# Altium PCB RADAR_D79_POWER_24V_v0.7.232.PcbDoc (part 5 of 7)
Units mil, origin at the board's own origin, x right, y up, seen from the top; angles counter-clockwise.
Board outline 3110.24 x 3110.24 mil, 8 copper layers (Top Layer, GND1, SIG1, PWR1, PWR2, SIG2, GND2, Bottom Layer), stack 55.2 mil thick; 304 components, 269 nets, 1408 pads, 1367 vias.
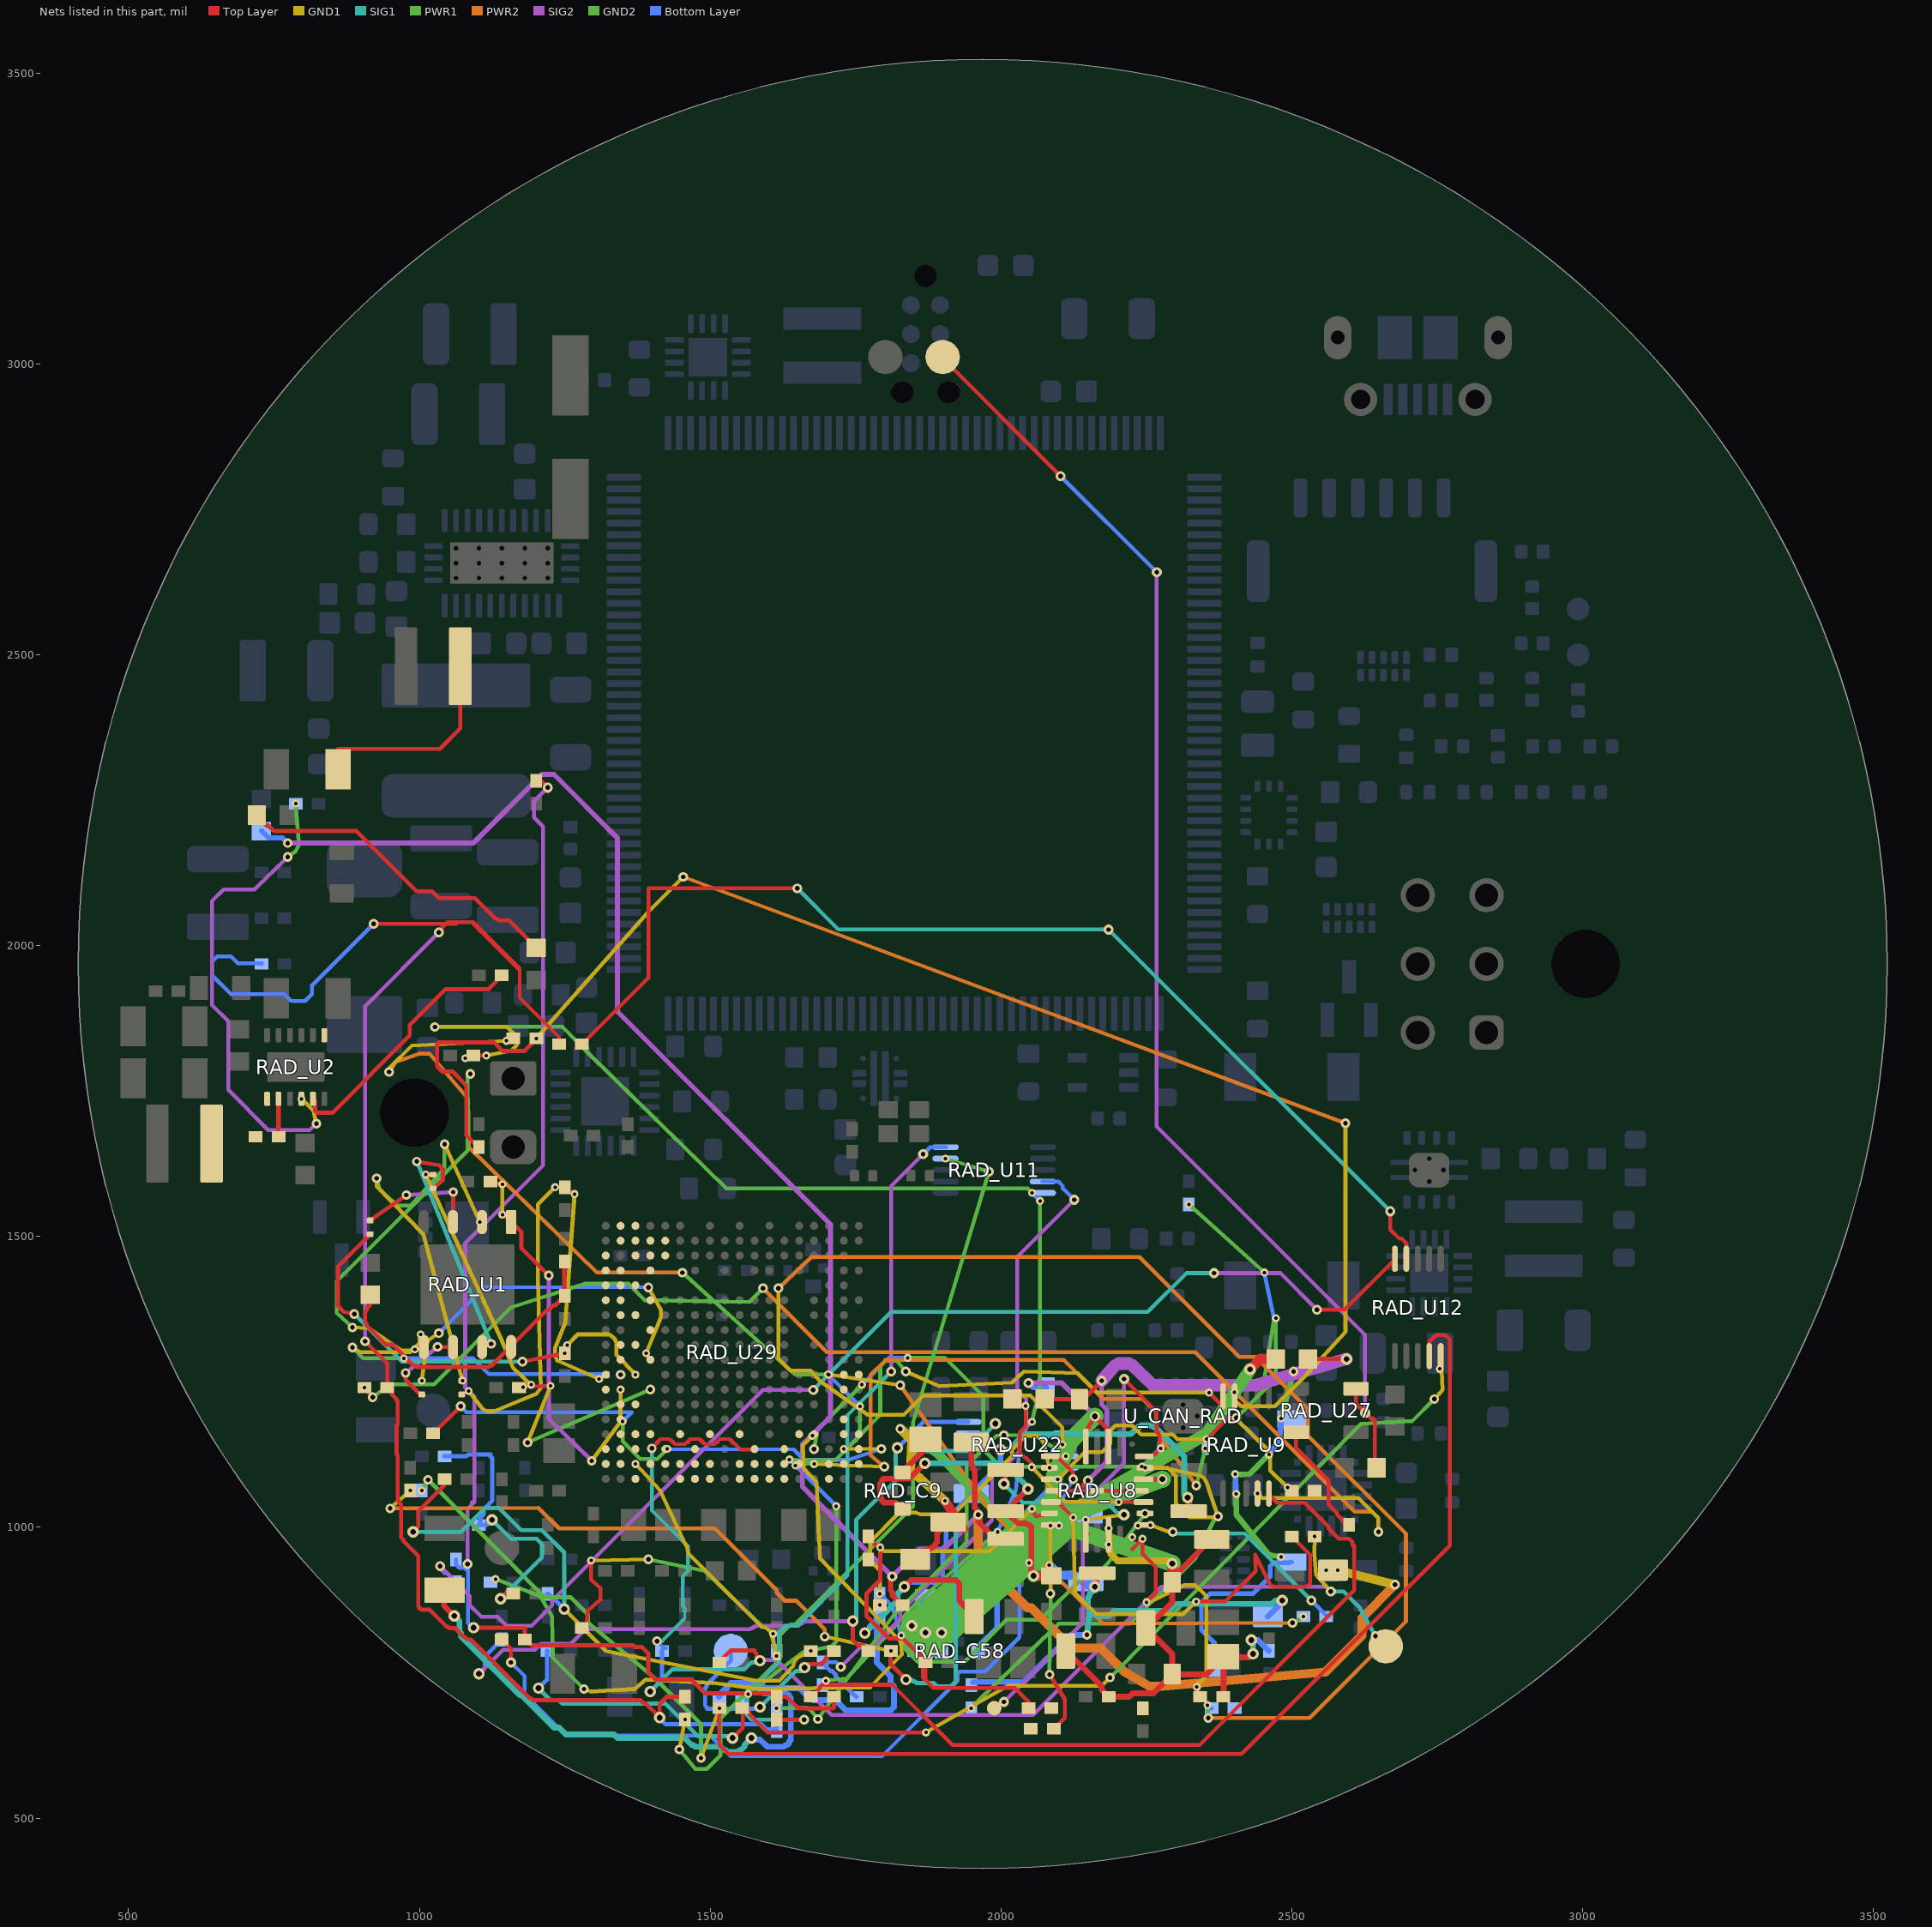
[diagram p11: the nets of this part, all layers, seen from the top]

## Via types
v1: diameter 13.77, hole 5.9, Top Layer to GND1, tented both sides, 393 vias
v2: diameter 16.54, hole 7.87, Top Layer to Bottom Layer, tented both sides, 129 vias
v3: diameter 19.68, hole 9.84, Top Layer to Bottom Layer, tented both sides, 126 vias
v4: diameter 13.77/13.77 (per signal layer), hole 5.9, Top Layer to GND1, tented both sides, 120 vias
v5: diameter 13.77, hole 5.9, Top Layer to GND1, tented top, 104 vias
v6: diameter 13.78, hole 5.91, Top Layer to GND1, tented both sides, 75 vias
v7: diameter 19.68, hole 9.84, Top Layer to Bottom Layer, 74 vias
v8: diameter 17.32, hole 7.87, Top Layer to Bottom Layer, tented both sides, 71 vias
v9: diameter 13.78, hole 5.91, GND2 to Bottom Layer, tented both sides, 64 vias
v10: diameter 13.78, hole 5.91, Top Layer to GND1, tented bottom, 39 vias
v11: diameter 13.78, hole 5.91, GND2 to Bottom Layer, tented top, 38 vias
v12: diameter 13.78, hole 5.91, Top Layer to GND1, 26 vias
v13: diameter 16.54, hole 7.87, GND2 to Bottom Layer, tented both sides, 22 vias
v14: diameter 16.54, hole 7.87, Top Layer to Bottom Layer, 19 vias
v15: diameter 22.05, hole 11.81, Top Layer to Bottom Layer, tented both sides, 17 vias
v16: diameter 13.78, hole 5.91, GND2 to Bottom Layer, 9 vias
v17: diameter 18.11, hole 9.06, Top Layer to Bottom Layer, 7 vias
v18: diameter 22.83, hole 11.81, Top Layer to Bottom Layer, 6 vias
v19: diameter 22.05, hole 11.81, Top Layer to Bottom Layer, 6 vias
v20: diameter 22.83, hole 11.81, Top Layer to Bottom Layer, tented both sides, 5 vias
v21: diameter 19.68, hole 7.87, Top Layer to Bottom Layer, 3 vias
v22: diameter 17.32, hole 8.66, Top Layer to Bottom Layer, 3 vias
v23: diameter 20.47, hole 9.84, Top Layer to Bottom Layer, 3 vias
v24: diameter 17.72, hole 9.84, Top Layer to Bottom Layer, tented both sides, 2 vias
v25: diameter 22.05, hole 11.02, Top Layer to Bottom Layer, 2 vias
v26: diameter 19.68, hole 11.81, Top Layer to Bottom Layer, 2 vias
v27: diameter 18, hole 9.84, Top Layer to Bottom Layer, tented both sides, 1 vias
v28: diameter 18.11, hole 9.06, Top Layer to Bottom Layer, tented both sides, 1 vias

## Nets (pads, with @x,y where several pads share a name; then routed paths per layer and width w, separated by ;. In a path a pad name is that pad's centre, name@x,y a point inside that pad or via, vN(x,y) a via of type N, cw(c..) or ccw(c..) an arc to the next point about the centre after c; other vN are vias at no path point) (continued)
TI_AGND: RAD_C3.1 RAD_C123.1 RAD_C124.1 RAD_NT1.2 RAD_NT2.1 RAD_NT3.1 RAD_NT4.1 RAD_U8.5 RAD_U8.5-19 RAD_U8.19 | length 1816.1
  Top Layer w7.09: RAD_C123.1@2074.8,1220.47 RAD_C124.1@2134.84,1220.47 ; RAD_U8.5@2088.58,1062.99 2131.89,1062.99 RAD_U8.19@2242.13,1062.99 ; RAD_C3.1@2527.56,1289.37 v7(2594,1289.37)
  Top Layer w7.87: 2126.97,1062.99 2125.98,1062.99 2131.89,1062.99 v8(2149.61,1080.71) ; RAD_C124.1@2134.84,1220.47 2134.84,1219.49 2140.75,1219.49 v8(2173.23,1251.97)
  SIG2 w7.87: v8(2149.61,1080.71) 2182.09,1113.19 2182.09,1201.77 2173.23,1210.63 v8(2173.23,1251.97)
  SIG2 w9.84: 2468.88,1253.31 v2(2502.95,1267.72)
  SIG2 w21.65: v8(2173.23,1251.97) 2195.08,1277.36 2201.97,1281.5 2219.88,1281.5 2225.39,1278.74 2261.22,1244.29 2437.6,1244.29 2468.88,1253.31 2504.17,1263.48 v7(2594,1289.37)
  GND2 w9.84: v9(2402.56,1091.54) 2412.4,1090.55 2427.17,1091.54 v9(2460.63,1125) ; v9(2404.53,1057.09) 2404.53,1021.65 2460.63,952.76 v11(2481.3,948.9) ; v11(2481.3,1187.01) v2(2502.95,1267.72)
  Bottom Layer w7.09: RAD_NT1.2@2496,940.2 RAD_NT1.2@2500,940.2
  Bottom Layer w7.87: RAD_NT4.1@2366.89,767.72 2368.11,767.72 2368.11,800.2 2344.49,823.82 2344.49,871.06 2359.25,885.83 2433.07,885.83 2462.6,915.35 2462.6,933.07 2468.5,938.98 2495.08,938.98 RAD_NT1.2@2496,940.2
  Bottom Layer w9.84: v9(2402.56,1091.54) v9(2404.53,1057.09) ; v9(2460.63,1125) 2478.35,1148.62 2481.3,1177.09 v11(2481.3,1187.01)
  Bottom Layer w11.81: RAD_NT3.1@2149.61,1021.65 v8(2149.61,1080.71)
TI_AR_NERROUT: RAD_R76.1 RAD_U29.C11 | length 1010.9
  PWR2 w6.69: v2(1826.77,1244.09) 1978.35,1031.5 2175.2,834.65 v2(2500.98,835.63)
  GND1 w6.69: v10(1704.16,1262.39) v2(1826.77,1244.09)
  GND2 w6.69: v2(2500.98,835.63) v11(2519.69,846.46)
TI_AR_NRST: RAD_C105.2 RAD_R99.1 RAD_R264.1 RAD_U29.H16 TP_RAD_RESET.1 | length 2378.5
  Top Layer w6.3: v2(1399.61,1135.63) 1406.69,1142.72 1406.69,1144.49 1408.46,1144.49 1408.46,1146.26 1410.24,1146.26 1410.24,1148.03 1412.01,1148.03 1412.01,1149.8 1413.78,1151.57 1429.72,1151.57 1431.5,1149.8 1433.27,1149.8 1433.27,1148.03 1435.04,1148.03 1435.04,1146.26 1436.81,1146.26 1436.81,1144.49 1438.58,1144.49 1440.35,1142.72 1456.3,1142.72 1459.84,1146.26 1461.61,1146.26 1461.61,1148.03 1463.39,1148.03 1463.39,1149.8 1465.16,1151.57 1481.1,1151.57 1482.87,1149.8 1484.65,1149.8 1484.65,1148.03 1486.42,1148.03 1486.42,1146.26 1488.19,1146.26 1488.19,1144.49 1489.96,1144.49 1491.73,1142.72 1507.68,1142.72 1511.22,1146.26 1512.99,1146.26 1512.99,1148.03 1516.54,1151.57 1532.48,1151.57 1534.25,1149.8 1536.02,1149.8 1536.02,1148.03 1537.8,1148.03 1537.8,1146.26 1539.57,1146.26 1539.57,1144.49 1541.34,1144.49 1551.97,1133.86 1576.77,1133.86 RAD_U29.H16@1576.21,1134.44
  Top Layer w7.09: RAD_R264.1@1515.75,767.72 1514.76,767.72 1535.43,788.39 1576.77,788.39 1576.77,785.43 1579.72,782.48 1579.72,776.57 v7(1585.63,770.67) ; v2(2643.7,812.99) TP_RAD_RESET.1@2661.42,795.28
  GND1 w6.69: v12(2539.37,984.25) 2538.39,953.74 2541.34,918.31 v8(2566.93,889.76)
  SIG1 w6.3: v2(1399.61,1135.63) 1399.61,1029.33 1461.61,967.32 1461.61,924.8 1452.76,915.94 1452.76,864.57 1456.3,861.02 1456.3,843.31 1417.32,804.33 v2(1408.46,804.33)
  SIG1 w7.09: v7(1396.65,717.52) 1435.04,755.91 1559.06,755.91 1570.87,767.72 1582.68,767.72 v7(1585.63,770.67) ; v8(2566.93,889.76) 2588.58,889.76 2616.14,862.2 v2(2643.7,812.99)
  SIG2 w6.69: v7(1585.63,770.67) 1586.61,771.65 1614.17,771.65 1708.66,677.17 2055.12,677.17 2275.59,897.64 2559.06,897.64 v8(2566.93,889.76)
  Bottom Layer w6.3: v2(1408.46,804.33) 1420.87,791.93 1424.41,791.93 RAD_C105.2@1424.61,792.72
  Bottom Layer w7.09: v7(1396.65,717.52) 1417.32,738.19 RAD_C105.2@1417.32,787.4 ; RAD_C105.2@1417.32,787.4 1417.32,788.39 RAD_C105.2@1417.32,787.4
TI_AR_WRMRST: RAD_U29.B12
TI_BSS_UARTA_TX: RAD_U29.M16
TI_CANA_NSTB: RAD_R13.1
TI_CANB_NSTB: RAD_R17.1
TI_CSI2_RX0_0_N: RAD_U29.N18
TI_CSI2_RX0_0_P: RAD_U29.N17
TI_CSI2_RX0_1_N: RAD_U29.M18
TI_CSI2_RX0_1_P: RAD_U29.M17
TI_CSI2_RX0_CLK_N: RAD_U29.L18
TI_CSI2_RX0_CLK_P: RAD_U29.L17
TI_DSS_UARTA_RX: RAD_U29.B14
TI_DSS_UARTA_TX: RAD_U29.A15
TI_FB_B1: RAD_R14.1 RAD_U8.3 | length 547.5
  GND1 w6.69: v6(1791.34,866.14) 1792.13,925.98 1774.8,943.31 1774.8,974.8 1825.2,1025.2 1853.54,1025.2 1861.42,1022.05 1918.11,1022.05 2018.9,1122.83 2018.9,1133.86 2042.52,1157.48 2061.42,1157.48 2072.44,1146.46 v6(2083.17,1102.36)
TI_FB_B2: RAD_R71.1 RAD_U8.21 | length 927.3
  GND1 w6.69: v6@2245.67,1100.79 2247.6,1100.86 2281.01,1102.15 ; v6(2247.54,1102.36) 2280.02,1102.36 2281.01,1102.15 ; v2@2368.5,1017.32 2324.41,1017.32 2300.79,1040.94 2300.79,1088.19 2288.44,1100.53 ; v2(2373.03,1018.7) 2352.85,1078.25 2349.9,1083.66 2343.5,1088.58 2288.44,1100.53 ; 2281.01,1102.15 2288.44,1100.53 ; 2281.01,1102.15 2286.61,1102.36 2288.44,1100.53
  GND2 w6.69: v9@1949.61,691.34 2099.21,834.65 2222.05,834.65 2333.86,946.46 v2@2368.5,1017.32
  other v9: 1948.82,688.98
TI_FB_B3: RAD_R291.1 RAD_U8.17 | length 644.3
  GND2 w6.69: v9(1828.35,814.17) 1828.35,796.85 1856.69,768.5 1937.01,768.5 2009.45,840.94 2067.72,840.94 2144.88,918.11 2163.78,918.11 2184.25,938.58 v2(2247.54,1023.62)
  Bottom Layer w6.69: v9(1791.34,885.83) 1812.6,864.57 v9(1828.35,814.17)
TI_GPADC1: RAD_U29.P3
TI_GPADC2: RAD_U29.P2
TI_GPADC3: RAD_U29.R3
TI_GPADC4: RAD_U29.R2
TI_GPADC5: RAD_U29.T3
TI_GPADC6: RAD_U29.U2
TI_GPADC7: RAD_U29.T1
TI_GPADC8: RAD_U29.T2
TI_GPADC9: RAD_U29.U1
TI_GPIO_3: RAD_U29.P16
TI_GPIO_4: RAD_U29.L15
TI_GPIO_8: RAD_U29.T18
TI_GPIO_9: RAD_U29.N15
TI_GPIO_30: RAD_U29.P17
TI_GPIO_31: RAD_U29.U17
TI_LVDS_TX0_N: RAD_U29.F18
TI_LVDS_TX0_P: RAD_U29.F17
TI_LVDS_TX1_N: RAD_U29.J18
TI_LVDS_TX1_P: RAD_U29.J17
TI_LVDS_TX2_CLK_N: RAD_U29.G18
TI_LVDS_TX2_CLK_P: RAD_U29.G17
TI_LVDS_TX3_FRCLK_N: RAD_U29.H18
TI_LVDS_TX3_FRCLK_P: RAD_U29.H17
TI_MCU_CLK_OUT: RAD_U29.R15
TI_MSS_EPWMA0: RAD_U29.E15
TI_MSS_EPWMA1: RAD_U29.C18
TI_MSS_EPWMB0: RAD_U29.C17
TI_MSS_GPIO_0: RAD_U29.B15
TI_MSS_GPIO_1: RAD_U29.A16
TI_MSS_GPIO_11: RAD_U29.J15
TI_MSS_GPIO_28: RAD_U29.R17
TI_MSS_I2CA_SCL: RAD_R27.2 RAD_R33.2 RAD_R57.2 RAD_R58.2 RAD_R276.1 | length 2325.4
  Top Layer w6.69: RAD_R276.1@1200.79,2283.46 1208.66,2283.46 v8(1220.47,2271.65)
  Top Layer w7.09: v7(1093,827.28) 1180,827.28 1181.1,826.18 RAD_R57.2@1181.1,807.09 1181.1,806.1 1187.01,800.2 1189.96,800.2 1192.91,797.24 1367.13,797.24 1370.08,794.29 1381.89,794.29 1393.7,782.48 1393.7,750 1405.51,738.19 1467.52,738.19 1491.14,714.57 1609.25,714.57 RAD_R33.2@1615.16,708.66 ; RAD_R27.2@1712.6,708.66 1712.6,690 1711.6,689 1651,689 1631.34,708.66 RAD_R33.2@1615.16,708.66 ; RAD_R33.2@1615.16,708.66 RAD_R33.2@1614.17,708.66 RAD_R33.2@1615.16,708.66
  SIG2 w6.69: v8(1082.68,937.01) 1082.68,1031.5 1090.55,1039.37 1090.55,1043.31 1094.49,1043.31 1094.49,1224.41 1078.74,1240.16 1078.74,1488.19 1212.6,1622.05 1212.6,2204.72 1196.85,2220.47 1196.85,2248.03 v8(1220.47,2271.65)
  Bottom Layer w6.69: v8(1082.68,937.01) 1082.68,927.17 1082.68,925.2 1083.66,927.16
  Bottom Layer w7.09: RAD_R58.2@1062.99,944.88 1062.99,937 1062.99,936.02 1068.9,930.12 1077.76,930.12 1080.71,927.17 1082.68,927.17 1083.66,927.17 1083.66,835.63 v7@1092.51,826.79 ; v7@1092.52,826.77 v7(1093,827.28)
TI_MSS_I2CA_SDA: RAD_R29.2 RAD_R35.2 RAD_R59.2 RAD_R62.2 RAD_R277.1 | length 3130.2
  Top Layer w6.3: v2(906.5,1319.88) 944.88,1281.5 RAD_R29.2@944.88,1240.16 ; v2(1033.46,2022.64) 1039.37,2028.54 1039.37,2031.5 1045.28,2037.4 1048.23,2040.35 1065.94,2040.35 1089.57,2040.35 1172.24,1957.68 1172.24,1910.43 1240.16,1842.52 RAD_R59.2@1240.16,1830.71
  Top Layer w6.69: v8(921.26,2037.4) 1045.28,2037.4 1062.99,2037.4 1065.94,2040.35 ; 1089.57,2040.35 1092.52,2040.35 1172.24,1960.63 1172.24,1957.68
  Top Layer w7.09: RAD_R29.2@944.88,1240.16 952.76,1232.28 952.76,1228.35 960.63,1220.47 960.63,1218.5 962.6,1216.54 962.6,1177.17 960.63,1175.2 960.63,1125.98 962.6,1124.02 962.6,1047.24 964.57,1045.28 964.57,1043.31 968.5,1039.37 968.5,982.28 972.44,978.35 972.44,976.38 998.03,950.79 998.03,864.17 1000,862.2 1000,860.24 1001.97,860.24 1003.94,858.27 1017.72,858.27 1047.24,828.74 1049.21,828.74 1051.18,826.77 1061.02,826.77 1076.77,811.02 1078.74,811.02 1082.68,807.09 1088.58,807.09 1188.98,706.69 1190.94,706.69 1194.88,702.76 1379.92,702.76 1383.86,698.82 1385.83,698.82 1387.8,696.85 1389.76,696.85 v7@1413,673.61 ; RAD_R35.2@1456.69,708.66 1425.5,708.66 1413,696.16 v7@1413,673.61 ; v7@1413,673.61 1413.39,673.23 v7(1413,672.68) v7@1413,673.61
  SIG2 w6.3: v2(906.5,1319.88) 906.5,1895.67 v2(1033.46,2022.64)
  Bottom Layer w6.69: RAD_R277.1@728.35,1968.5 729.33,1969.49 687.99,1969.49 676.18,1981.3 652.56,1981.3 643.7,1972.44 643.7,1948.82 676.18,1916.34 767.72,1916.34 779.53,1904.53 803.15,1904.53 814.96,1916.34 814.96,1931.1 v8(921.26,2037.4)
  Bottom Layer w7.09: v7(1413,672.68) 1414.37,673.23 1417.32,670.28 1417.32,667.32 1423.23,661.42 1588.58,661.42 1597.44,652.56 1612.2,652.56 RAD_R62.2@1614.17,650.59 ; 1613,664.76 1614.17,663.59 RAD_R62.2@1614.17,650.59 ; RAD_R62.2@1614.17,650.59 RAD_R62.2@1614.17,649.61 1615.16,649.61 RAD_R62.2@1614.17,650.59
TI_MSS_MCANA_RX: RAD_U29.D16 U_CAN_RAD.4 | length 818.4
  GND2 w6.69: v14(1678.57,1134.44) 1685.04,1169.29 v9(1760.83,1245.08) ; v9(1839.57,1291.34) 1903.54,1291.34 1969.49,1225.39 1969.49,1133.86 1999.02,1104.33 v9(2242.13,1104.33)
  Bottom Layer w6.69: v9(1760.83,1245.08) 1807.09,1291.34 v9(1839.57,1291.34) ; v9(2242.13,1104.33) U_CAN_RAD.4@2273.23,1135.83
  other v11: 2274.61,1135.83
TI_MSS_MCANA_TX: RAD_U29.D17 U_CAN_RAD.1 | length 1042.8
  PWR2 w6.69: v2(1799.21,1104.33) 1775.59,1124.02 1775.59,1261.81 1801.18,1287.4 2108.27,1287.4 2175.2,1220.47 2244.09,1220.47 2267.72,1196.85 2267.72,1163.39 v2(2335.63,1071.85)
  GND1 w6.69: v10(1678.57,1108.85) v2(1799.21,1104.33)
  GND2 w6.69: v2(2335.63,1071.85) v11(2351.38,1135.83)
TI_MSS_MCANB_RX: RAD_U29.A17
TI_MSS_MCANB_TX: RAD_U29.B17
TI_MSS_MDIO_CLK: RAD_U29.R4
TI_MSS_MDIO_DATA: RAD_U29.T5
TI_MSS_RGMII_RCLK: RAD_U29.T9
TI_MSS_RGMII_RCTL: RAD_U29.T7
TI_MSS_RGMII_RD0: RAD_U29.V6
TI_MSS_RGMII_RD1: RAD_U29.V4
TI_MSS_RGMII_RD2: RAD_U29.V5
TI_MSS_RGMII_RD3: RAD_U29.U10
TI_MSS_RGMII_TCLK: RAD_U29.V3
TI_MSS_RGMII_TCTL: RAD_U29.R6
TI_MSS_RGMII_TD0: RAD_U29.U7
TI_MSS_RGMII_TD1: RAD_U29.U5
TI_MSS_RGMII_TD2: RAD_U29.U6
TI_MSS_RGMII_TD3: RAD_U29.U4
TI_MSS_RS232RX: RAD_U29.F16
TI_MSS_RS232TX: RAD_U29.E17
TI_MSS_SPIA_CLK: RAD_U29.T16
TI_MSS_SPIA_CS0: RAD_U29.T15
TI_MSS_SPIA_HOSTIRQ: RAD_U29.V17
TI_MSS_SPIA_MOSI: RAD_U29.U15
TI_MSS_SPIB_CS0: RAD_U29.U14
TI_MSS_SPIB_CS1: RAD_U29.V16
TI_MSS_SPIB_MISO: RAD_U29.U13
TI_MSS_UARTA_RX: RAD_R129.1 RAD_U29.B16 | length 962.1
  Top Layer w6.69: RAD_R129.1@1023.62,1161.42 1024.02,1161.22 v14(1070.87,1208.07)
  GND1 w6.3: v10(1729.75,1134.44) v14(1794.29,1134.84)
  GND2 w6.69: v16(1349.41,1182.09) 1349.41,1147.64 1379.92,1117.13 1408.46,1117.13 v16(1426.18,1134.84)
  Bottom Layer w6.69: v14(1070.87,1208.07) 1080.91,1198.03 1365.35,1198.03 v16(1349.41,1182.09) ; v16(1426.18,1134.84) 1428.94,1134.45 1643.7,1133.86 1661.42,1116.14 1738.19,1116.14 v14(1794.29,1134.84)
TI_NERR_MCU: RAD_R76.2 RAD_U8.16 | length 388.5
  Top Layer w6.69: v6(2235.24,1002.95) 2246.08,1003.34 v6(2257.09,1003.74) ; RAD_U8.16@2246.06,1003.94 RAD_U8.16@2247.05,1003.94
  GND1 w6.69: v6(2257.09,1003.74) 2294.54,990.1 v14@2297.64,988.98
  SIG1 w6.69: v14@2297.64,988.98 2418.9,988.98 v8(2533.46,874.02)
  Bottom Layer w6.69: v8(2533.46,874.02) 2560.04,847.44 RAD_R76.2@2559.06,846.46
  other v14: 2295.28,992.13
TI_NetC1_2: RAD_C1.2 RAD_C2.2 RAD_R37.2 RAD_U1.8 | length 540
  Top Layer w7.09: RAD_C1.2@915.35,1399.61 915.35,1381.89 909.45,1375.98 909.45,1373.03 906.5,1370.08 906.5,1352.36 909.45,1349.41 909.45,1346.46 941.93,1313.98 953.74,1313.98 989.17,1278.54 992.13,1278.54 995.08,1275.59 1119.09,1275.59 1122.05,1278.54 1125,1278.54 RAD_U1.8@1157.48,1311.02 ; RAD_U1.8@1157.68,1309.98 RAD_U1.8@1157.48,1311.02 ; RAD_C2.2@1250,1397.64 RAD_C2.2@1249.02,1396.65 ; RAD_R37.2@1250,1456.69 1249.02,1455.71 RAD_C2.2@1249.02,1396.65 ; RAD_U1.8@1157.48,1311.02 1219.49,1373.03 1222.44,1373.03 1231.3,1381.89 1234.25,1381.89 RAD_C2.2@1249.02,1396.65
TI_NetC14_1: RAD_C14.1 RAD_R26.2 RAD_U9.9 | length 2626
  Top Layer w6.69: RAD_U9.9@2401.57,1225.39 v12(2401.57,1232.28)
  Top Layer w7.09: RAD_R26.2@1102.36,1653.54 1101.38,1653.54 1080.71,1674.21 1080.71,1759.84 1057.09,1783.46 1039.37,1783.46 1030.51,1792.32 1030.51,1830.71 1033.46,1833.66 1127.95,1833.66 1142.72,1818.9 1181.1,1818.9 1201.77,1839.57 v12(1200.79,1840.55)
  PWR2 w6.69: v2(1453.54,2118.11) v2(2592.13,1694.49)
  GND1 w6.69: v12(1200.79,1840.55) 1392.13,2056.69 v2(1453.54,2118.11) ; v12(2401.57,1232.28) 2401.57,1218.9 2412.6,1207.87 2470.87,1207.87 2521.26,1258.27 2592.13,1335.43 v2(2592.13,1694.49)
TI_NetC14_2: RAD_C14.2 RAD_R32.2 RAD_U9.10 | length 3012.8
  Top Layer w6.69: v6(1149.61,1836.22) 1161.22,1835.74 RAD_C14.2@1168.5,1835.43 ; v6(2357.48,1231.5) 2372.84,1216.27 2381.69,1207.48 RAD_U9.10@2381.69,1225.39
  PWR2 w6.69: v2(948.03,1782.68) 959.06,1800 1000,1814.17 1017.32,1814.17 1083.46,1737.01 1085.04,1653.54 1305.51,1437.8 v2(1451.97,1437.8)
  GND1 w6.69: v2(948.03,1782.68) 948.03,1788.98 987.4,1828.35 v6(1149.61,1836.22) ; v2(1836.22,1267.72) 1894.49,1242.52 2018.9,1248.82 2039.37,1267.72 2132.28,1264.57 2165.35,1231.5 v6(2357.48,1231.5)
  GND2 w6.69: v2(1451.97,1437.8) 1645.67,1262.99 v9(1702.36,1262.99) ; v11(1565.35,713.39) 1659.84,785.83 1708.66,795.28 1716.54,803.15 v9(1716.54,1036.22) ; v9(1636.22,1116.54) 1647.06,1116.08 1674.02,1114.96 1707.28,1114.96 ; v9(1646.65,1106.3) 1707.28,1114.96 ; v9(1757.48,1207.87) 1757.48,1158.07 ; v2(1836.22,1267.72) 1820.47,1286.61 1801.57,1286.61 1792.32,1277.56 1792.32,1192.91 1757.48,1158.07 ; 1707.28,1114.96 1714.96,1114.96 1757.48,1157.48 1757.48,1158.07 ; 1707.28,1114.96 1715.55,1116.14 1757.48,1158.07
  Bottom Layer w6.69: RAD_R32.2@1562.2,713.78 v11(1565.35,713.39) ; v9(1646.65,1106.3) v9(1636.22,1116.54) v9(1716.54,1036.22) ; v9(1702.36,1262.99) v9(1757.48,1207.87)
TI_NetC17_1: RAD_C17.1 RAD_R47.2 RAD_U11.9 | length 1192.1
  SIG2 w6.69: v8(1724.41,759.84) 1759.84,795.28 1779.53,795.28 1826.77,842.52 1826.77,854.33 1984.25,1011.81 1984.25,1090.55 2003.94,1110.24 2011.81,1110.24 2031.5,1129.92 2031.5,1157.48 2043.31,1169.29 2043.31,1220.47 2027.56,1236.22 2027.56,1464.57 v8(2125.98,1562.99)
  Bottom Layer w6.69: RAD_C17.1@1692.91,767.72 1716.54,767.72 v8(1724.41,759.84) ; RAD_U11.9@2071.85,1594.49 2070.87,1594.49 2098.43,1594.49 2106.3,1586.61 2106.3,1582.68 v8(2125.98,1562.99)
  Bottom Layer w7.09: RAD_C17.1@1692.91,767.72 1691.93,767.72 1692.42,767.22 1706.69,752.95 1709.65,752.95 1715.55,747.05 1715.55,744.09 1750.98,708.66 RAD_R47.2@1751.97,708.66
TI_NetC17_2: RAD_C17.2 RAD_R65.2 RAD_U11.10 | length 2403.8
  Top Layer w6.69: v6(1078.74,1806.3) 1092.43,1806.04 RAD_R65.2@1099.61,1805.91 ; RAD_R65.2@1099.61,1811.02 v6(1115.16,1811.02)
  GND1 w6.69: v2(1026.57,1860.24) 1150.59,1860.24 1167.32,1843.5 1167.32,1828.74 1157.48,1818.9 v6(1115.16,1811.02)
  GND2 w6.69: v2(1026.57,1860.24) 1246.06,1860.24 1292.91,1812.6 1527.56,1582.68 2045.67,1582.68 v11(2053.54,1574.8) ; v11(1698.82,736.22) 1734.25,740.16 1856.3,872.05 v9(1994.09,992.13) ; v9(2053.15,1181.1) 2066.93,1240.16 v9(2066.93,1561.02)
  Bottom Layer w6.69: RAD_C17.2@1698.03,735.43 v11(1698.82,736.22) ; v9(1994.09,992.13) 2025.59,1064.96 2033.46,1161.42 v9(2053.15,1181.1) ; v11(2053.54,1574.8) RAD_U11.10@2053.94,1575 ; RAD_U11.10@2053.94,1574.61 2062.4,1565.76 v9(2066.93,1561.02)
TI_NetC19_1: RAD_C19.1 RAD_R348.2 RAD_U12.9 | length 2714.4
  Top Layer w6.69: v10(1515.75,688.98) 1515.75,625.98 1531.5,610.24 2413.39,610.24 2771.65,968.5 2771.65,1322.83 2763.78,1330.71 2748.03,1330.71 2736.22,1318.9 2736.22,1295.28 RAD_U12.9@2736.22,1294.29
  PWR1 w7.09: v2(1014.76,1081.69) 1214.57,879.92 1259.84,879.92 1289.37,850.39 1289.37,836.61 1407.48,738.19 1484.25,661.42 v2(1484.25,603.35)
  GND1 w6.69: v2(1484.25,603.35) v10(1515.75,688.98)
  GND2 w6.69: v11(1003.94,1062.99) v2(1014.76,1081.69)
TI_NetC19_2: RAD_C19.2 RAD_R352.2 RAD_U12.10 | length 1995.2
  Top Layer w6.69: RAD_C19.2@1562.2,694.09 1563.02,691.91 1568.5,677.17 1598.43,647.24 v6(1870.87,647.24) ; v10(2754.33,1272.44) RAD_U12.10@2755.71,1276.38
  Top Layer w7.09: v7(1538.39,637.8) 1556.1,655.51 1556.1,687.99 RAD_C19.2@1555.12,688.98
  PWR1 w6.69: v2(2187.4,741.73) 2618.9,1177.95 2707.09,1182.68 v2(2744.88,1220.47)
  GND1 w6.69: v6(1870.87,647.24) 2012.6,727.56 2173.23,727.56 v2(2187.4,741.73) ; v2(2744.88,1220.47) 2759.06,1236.22 2757.48,1269.29 v10(2754.33,1272.44)
  SIG1 w7.09: v7(1204.72,723.43) 1225.39,702.76 1240.16,702.76 1246.06,696.85 1423.23,696.85 1479.33,640.75 1535.43,640.75 v7(1538.39,637.8)
  Bottom Layer w7.09: v7(1204.72,723.43) 1219.49,738.19 1219.49,788.39 RAD_R352.2@1220.47,787.4
TI_NetC21_1: RAD_C21.1 RAD_U2.2 | length 65.2
  Top Layer w8: RAD_C21.1@757.87,1671.39 RAD_U2.2@757.87,1736.61
TI_NetC21_2: RAD_C21.2 RAD_L6.1 RAD_U2.1
TI_NetC81_1: RAD_C81.1 RAD_R56.2 RAD_U22.9 | length 1806.5
  Top Layer w7.09: v10(1811.02,787.4) 1810.04,788.39 1810.04,764.76 v7(1836.61,738.19)
  PWR2 w7.09: v2(949.8,1032.48) 1204.72,1033.46 1240.16,998.03 1507.87,998.03 1614.17,891.73 1614.17,887.8 1627.95,874.02 1647.64,874.02 1696.85,824.8 v2(1696.85,812.01)
  GND1 w6.69: v2(949.8,1032.48) v10(984.25,1062.99) ; v2(1696.85,812.01) v10(1811.02,787.4)
  SIG1 w7.09: v7(1836.61,738.19) 1845.47,738.19 1848.43,735.24 1851.38,735.24 1854.33,732.28 1883.86,732.28 1889.76,726.38 1913.39,726.38 1922.24,735.24 1922.24,1024.61 1848.43,1098.43 1848.43,1122.05 1857.28,1130.91 1942.91,1130.91 v7(1990.16,1178.15)
  Bottom Layer w7.09: RAD_U22.9@1943.9,1161.42 1942.91,1160.43 1972.44,1160.43 v7(1990.16,1178.15)
TI_NetC81_2: RAD_C81.2 RAD_R66.2 RAD_U22.10 | length 1295.4
  Top Layer w7.09: v7(1745.08,838.58) 1745.08,806.1 1753.94,797.24 1762.8,797.24 1771.65,788.39 RAD_C81.2@1771.65,787.4
  SIG1 w7.09: v7(1745.08,838.58) 1750.98,844.49 1750.98,1012.8 1818.9,1080.71 1818.9,1133.86 v7(1821.85,1136.81)
  SIG2 w7.09: v3(1102.36,748.03) 1143.7,789.37 1198.82,789.37 1208.66,799.21 1259.84,799.21 1285.43,824.8 1568.9,824.8 1570.87,826.77 1572.83,826.77 1574.8,828.74 1576.77,828.74 1578.74,830.71 1651.57,830.71 1655.51,834.65 1657.48,834.65 1661.42,838.58 v7(1745.08,838.58) ; v7(1745.08,838.58) 1746.06,838.58 v7(1745.08,838.58)
  Bottom Layer w7.09: v3(1102.36,748.03) 1112.2,757.87 1112.2,777.56 RAD_R66.2@1141.73,807.09 ; v7(1821.85,1136.81) 1866.14,1181.1 1942.91,1181.1 RAD_U22.10@1943.9,1181.1
TI_NetC100_1: RAD_C100.1 RAD_L5.1 | length 366.7
  Top Layer w7.09: RAD_C100.1@860.24,2303.15 860.24,2338.24 1035.24,2338.24 1070.28,2373.28 RAD_L5.1@1070.28,2480.32
TI_NetC104_1: RAD_C104.1 RAD_C126.1 | length 577.4
  Top Layer w7.09: RAD_C104.1@720.47,2224.41 720.47,2223.43 738.19,2205.71 741.14,2205.71 750,2196.85 891.73,2196.85 995.08,2093.5 1021.65,2093.5 1033.46,2081.69 1095.47,2081.69 1130.91,2046.26 1133.86,2046.26 1136.81,2043.31 1154.53,2043.31 1201.77,1996.06 RAD_C126.1@1200.79,1996.06
TI_NetC123_2: RAD_C123.2 RAD_U8.18 | length 362
  Top Layer w6.69: RAD_C123.2@2019.69,1220.47 v6(2042.32,1208.66) 2042.32,1173.23 2032.48,1163.39 2032.48,1127.95 2040.35,1120.08 2043.31,1119.09 2052.66,1110.24 v12(2052.66,1103.35) ; v12(2202.26,1043.31) RAD_U8.18@2233.07,1043.5
  Top Layer w7.09: RAD_U8.18@2233.07,1043.5 2233.07,1043.31 RAD_U8.18@2245.08,1043.31
  GND1 w6.69: v12(2052.66,1103.35) 2110.24,1044.09 v12(2202.26,1043.31)
TI_NetC149_2: RAD_C149.2 RAD_P1.2 RAD_U27.5 | length 2302.7
  Top Layer w6.69: RAD_P1.2@1899.61,3011.81 1897.64,3011.81 v8(2102.36,2807.09) ; v8(2625.98,1196.85) 2610.24,1212.6 2610.24,1213.58 2610.24,1237.2 RAD_U27.5@2610.24,1238.19 ; RAD_U27.5@2610.24,1238.19 2610.24,1240.16 RAD_U27.5@2610.24,1238.19
  Top Layer w7.09: 2610.24,1213.58 2636.81,1187.01 2639.76,1187.01 2639.76,1184.06 2642.72,1184.06 2642.72,1104.33 2645.18,1101.87 2645.67,1101.38 RAD_C149.2@2645.67,1102.36 ; RAD_U27.5@2610.24,1237.2 RAD_U27.5@2610.24,1238.19
  SIG2 w6.69: v8(2267.72,2641.73) 2267.72,1688.98 2625.98,1330.71 v8(2625.98,1196.85)
  Bottom Layer w6.69: v8(2102.36,2807.09) v8(2267.72,2641.73)
TI_NetJ17_1: RAD_R300.2 TP_RAD_FLASH.1 | length 383.7
  Top Layer w7.09: v3(1662.4,758.86) 1668.31,764.76 1691.93,764.76 1697.83,770.67 1697.83,773.62 1712.6,788.39 RAD_R300.2@1712.6,787.4
  SIG1 w7.09: v3(1585.63,690.94) 1647.64,752.95 1656.5,752.95 v3(1662.4,758.86)
  Bottom Layer w7.09: v3(1585.63,690.94) 1582.68,687.99 1494.09,687.99 1494.09,690.94 1491.14,693.9 1491.14,723.43 1494.09,726.38 1494.09,729.33 1535.43,770.67 TP_RAD_FLASH.1@1535.43,787.4 ; TP_RAD_FLASH.1@1535.43,787.4 1535.43,788.39 TP_RAD_FLASH.1@1535.43,787.4
TI_NetL1_1: RAD_L1.1 RAD_U8.11 | length 325.7
  Top Layer w7.09: v3(2004.92,1074.8) 2007.87,1077.76 RAD_L1.1@2007.87,1098.43 ; RAD_U8.11@2145.67,987.2 2146.65,986.22 RAD_U8.11@2149.61,989.17
  GND1 w7.09: v12(2145.67,1012.8) v3(2211.61,1021.65)
  SIG1 w7.09: v3(2004.92,1074.8) 2037.4,1042.32 2182.09,1042.32 2199.8,1024.61 2208.66,1024.61 v3(2211.61,1021.65)
TI_NetR1_1: RAD_R1.1 RAD_U2.5 | length 455.2
  Top Layer w7.09: RAD_U2.5@816.93,1736.61 817.91,1736.22 820.87,1733.27 820.87,1715.55 823.82,1712.6 850.39,1712.6 983.27,1845.47 983.27,1863.19 1045.28,1925.2 1119.09,1925.2 1142.72,1948.82 RAD_R1.1@1141.73,1948.82
TI_NetR2_2: RAD_R2.2 RAD_U2.4 | length 833.4
  GND1 w6.69: v10(797.24,1736.61) 817.91,1715.55 v2(822.83,1693.9)
  SIG2 w6.69: v2(773.62,2152.56) 716.54,2096.46 663.39,2096.46 643.7,2076.77 643.7,1897.64 671.26,1870.08 671.26,1751.97 740.16,1683.07 811.02,1683.07 v2(822.83,1693.9)
  GND2 w6.69: v2(773.62,2152.56) 787.4,2162.4 792.32,2171.26 792.32,2180.12 v11(787.4,2244.09)
TI_NetR3_2: RAD_U29.U9
TI_NetR4_2: RAD_U2.7
TI_NetR27_1: RAD_R27.1 RAD_U9.5 | length 1364.9
  Top Layer w6.69: RAD_R27.1@1673.23,708.66 1674.21,708.66 1688.98,723.43 1688.98,726.38 1691.93,729.33 1812.99,729.33 1916.34,625.98 2341.54,625.98 2607.28,891.73 2607.28,968.5 2604.33,968.5 2604.33,974.41 2598.43,980.32 2580.71,980.32 2562.99,998.03 2562.99,1000.98 2521.65,1042.32 2474.41,1042.32 2459.65,1057.09 RAD_U9.5@2460.63,1058.07
TI_NetR29_1: RAD_R29.1 RAD_U9.4 | length 2277.2
  Top Layer w6.69: v6(905.51,1240.16) v2(919.68,1223.62)
  PWR1 w6.69: v2(919.68,1223.62) 949.61,1245.67 1025.2,1245.67 1157.48,1377.95 1285.04,1418.9 1359.06,1418.9 1387.4,1390.55 1566.93,1387.4 v2(1590.55,1411.02)
  PWR2 w6.69: v2(1590.55,1411.02) 1700.79,1300.79 2333.86,1300.79 2607.87,1026.77 2637.8,1026.77 2648.82,1015.75 v2(2648.82,992.13)
  GND1 w6.69: v6(2440.94,1058.07) 2448.82,1050.39 2614.17,1050.39 2648.82,1015.75 v2(2648.82,992.13)
TI_NetR31_2: RAD_U29.R8
TI_NetR33_1: RAD_R33.1 RAD_U11.5 | length 1295.8
  Top Layer w6.69: RAD_R33.1@1614.17,669.29 v8(1661.42,669.29)
  SIG1 w6.69: v8(1661.42,669.29) 1570.87,669.29 1562.99,677.17 1562.99,712.6 1618.11,767.72 1618.11,818.9 1629.92,830.71 1649.61,830.71 1736.22,917.32 1736.22,1192.91 v8(1811.02,1267.72)
  SIG2 w6.69: v8(1811.02,1267.72) 1811.02,1586.61 v8(1866.14,1641.73)
  Bottom Layer w6.69: v8(1866.14,1641.73) 1877.95,1653.54 RAD_U11.5@1904.53,1653.54 ; RAD_U11.5@1904.53,1653.54 1905.51,1653.54 RAD_U11.5@1904.53,1653.54
TI_NetR35_1: RAD_R35.1 RAD_U11.4 | length 1390.7
  PWR1 w6.69: v2(1446.85,618.11) 1474.41,584.65 1494.09,584.65 1517.72,608.27 1517.72,671.26 1620.08,773.62 1620.08,814.96 1637.8,832.68 1645.67,832.68 1848.43,1035.43 1848.43,1179.13 v2(1979.33,1611.22)
  GND1 w6.69: v2(1446.85,618.11) v10(1456.69,669.29)
  GND2 w6.69: v11(1904.53,1633.86) v2(1979.33,1611.22)
TI_NetR57_1: RAD_R57.1 RAD_U22.5 | length 1421.9
  Top Layer w6.69: RAD_R57.1@1141.73,807.09 1157.48,791.34 v8(1157.48,767.72)
  Bottom Layer w6.69: v8(1157.48,767.72) 1181.1,744.09 1181.1,712.6 1251.97,641.73 1500,641.73 1535.43,606.3 1795.28,606.3 1925.2,736.22 1925.2,748.03 1929.13,751.97 1972.44,751.97 2031.5,811.02 2031.5,1015.75 2110.24,1094.49 2110.24,1102.36 RAD_U22.5@2111.22,1102.36
TI_NetR58_1: RAD_R58.1 RAD_U12.5 | length 2053.3
  Top Layer w6.69: v8(2543.31,1374.02) 2590.55,1374.02 2677.17,1460.63 RAD_U12.5@2677.17,1461.61
  SIG1 w6.69: v8(1677.17,1236.22) 1811.02,1370.08 2251.97,1370.08 2318.9,1437.01 v8(2366.14,1437.01)
  SIG2 w6.69: v8(1035.43,933.07) 1086.61,881.89 1086.61,866.14 1106.3,846.46 1133.86,846.46 1149.61,830.71 1192.91,830.71 1228.35,866.14 1228.35,874.02 1590.55,1236.22 v8(1677.17,1236.22) ; v8(2366.14,1437.01) 2480.32,1437.01 v8(2543.31,1374.02)
  Bottom Layer w6.69: v8(1035.43,933.07) 1035.43,929.13 1043.31,921.26 1047.24,921.26 RAD_R58.1@1062.99,905.51
TI_NetR59_1: RAD_R59.1 RAD_U12.4 | length 1917.9
  Top Layer w6.69: RAD_R59.1@1279.53,1830.71 1393.7,1944.88 1393.7,2098.43 v14(1649.61,2098.43) ; v8(2669.29,1543.31) 2669.29,1511.81 2685.04,1496.06 2688.98,1496.06 2696.85,1488.19 RAD_U12.4@2696.85,1461.61 ; RAD_U12.4@2696.85,1461.61 2696.85,1460.63 RAD_U12.4@2696.85,1461.61
  SIG1 w6.69: v14(1649.61,2098.43) 1720.47,2027.56 v8(2185.04,2027.56) v8(2669.29,1543.31)
TI_NetR62_1: RAD_R62.1 RAD_U22.2 RAD_U22.4 | length 913.7
  PWR1 w6.69: v2(1685.04,670.28) 1814.96,848.43 1940.94,974.41 1940.94,1106.3 1992.13,1157.48 v2(2004.92,1158.46)
  GND2 w6.69: v11(1614.17,688.98) 1666.34,688.98 1673.23,685.04 v2(1685.04,670.28) ; v2(2004.92,1158.46) 2060.04,1157.48 v11(2111.22,1122.05)
  Bottom Layer w7.09: v11(2111.22,1122.05) 2108.27,1125 2081.69,1125 2075.79,1130.91 2075.79,1151.57 2078.74,1154.53 2078.74,1157.48 2108.27,1157.48 2111.22,1160.43 RAD_U22.2@2111.22,1161.42
TI_NetR63_1: RAD_R63.1 RAD_U8.1 | length 2624.5
  PWR2 w6.69: v2(1617.32,1411.02) 1674.02,1464.57 2237.8,1464.57 2409.45,1292.91 2437.8,1292.91 2527.56,1203.15 2527.56,1157.48 2696.06,988.98 2696.06,837.8 2530.71,672.44 v14(2356.3,672.24)
  GND1 w6.69: v2(1617.32,1411.02) 1617.32,1289.76 1637.8,1269.29 1672.44,1269.29 1689.76,1250.39 1770.08,1193.7 1833.07,1193.7 1866.14,1226.77 2050.39,1226.77 2105.51,1171.65 v6(2105.58,1142.22)
  GND2 w6.69: v9(2355.12,694.09) v14(2356.3,672.24)
  Bottom Layer w7.09: v9(2355.12,694.09) 2360.24,688.98 RAD_R63.1@2362.2,688.98
TI_NetR159_2: RAD_R409.1 RAD_U27.3 | length 200.1
  Top Layer w7.09: RAD_U27.3@2507.87,1163.39 2506.89,1163.39 2506.89,1136.81 2562.99,1080.71 2562.99,1039.37 2577.76,1024.61 2577.76,1021.65 2592.52,1006.89 2595.47,1006.89 RAD_R409.1@2598.43,1003.94
TI_NetR186_1: RAD_R186.1 RAD_U8.8 | length 380.3
  Top Layer w7.09: v2(2083.46,746.85) 2109.65,704.13 2109.65,672.44 RAD_R186.1@2090.55,653.54 ; RAD_U8.8@2084.65,1003.74 v6(2084.65,1002.95) v6(2099.41,1002.95)
  PWR1 w6.69: v2(2083.46,746.85) v2@2085.04,881.89
  GND1 w6.69: v6(2084.65,1002.95) 2085.03,886.02 v2@2085.04,881.89
  other v2: 2084.84,886.02
TI_NetR190_2: RAD_R190.2 RAD_R292.2 RAD_U8.4 | length 1204.4
  Top Layer w6.69: v6(2353.35,1151.57) 2389.76,1187.99 v14(2404.72,1188.19)
  Top Layer w7.09: RAD_U8.4@2085.63,1082.68 2097.52,1082.68 2097.84,1083 2098,1082.84 v6(2097.64,1082.48) ; v6(2492.91,1068.11) 2498.03,1062.99 RAD_R190.2@2500,1062.99
  GND1 w6.69: v6(2097.64,1082.48) 2143.7,1128.94 2173.23,1128.94 2187.99,1143.7 2187.99,1166.34 2196.85,1175.2 2225.39,1175.2 2241.14,1159.45 2295.28,1159.45 2303.15,1151.57 v6(2353.35,1151.57) ; v14@2404.72,1185.83 2462.99,1129.13 2462.99,1097.64 v6@2491.34,1069.29
  GND2 w6.69: v16(2322.83,1555.12) v9(2452.76,1437.99) ; v9@2469.49,1358.27 2448.82,1232.28 v14(2404.72,1188.19) 2472.44,1255.91 v9(2472.44,1359.25)
  Bottom Layer w6.69: v9(2452.76,1437.99) v9@2469.49,1358.27
TI_NetR193_1: RAD_R193.1 RAD_U8.2 | length 464.5
  Top Layer w6.69: RAD_U8.2@2095.67,1121.85 2124.02,1094.49 v14(2124.02,1082.68)
  GND2 w6: v11(1857.83,792.87) 1902.56,793.31 v9(2048.23,938.98)
  Bottom Layer w6: v9(2048.23,938.98) v14@2123.03,1081.69
  Bottom Layer w6.69: v14@2123.03,1081.69 v14(2124.02,1082.68)
TI_NetR298_1: RAD_R299.2 RAD_R300.1 RAD_R302.2 | length 1044.5
  Top Layer w7.09: v3(989.17,992.13) 998.03,1000.98 998.03,1027.56 1042.32,1071.85 1042.32,1083.66 RAD_R299.2@1043.31,1082.68
  GND1 w6.69: v3(1249.02,859.25) 1320.87,787.4 1574.8,737.2 1592.52,736.22 1619.09,736.22 1642.72,761.81 1643.7,767.72 1649.61,775.59 v10(1673.23,787.4)
  SIG1 w7.09: v3(989.17,992.13) 1071.85,992.13 1113.19,1033.46 1136.81,1033.46 1175.2,995.08 1210.63,995.08 1249.02,956.69 v3(1249.02,859.25)
  Bottom Layer w7.09: v3(1249.02,859.25) 1222.44,885.83 RAD_R302.2@1220.47,885.83 ; RAD_R302.2@1220.47,885.83 1219.49,885.83 RAD_R302.2@1220.47,885.83
TI_NetR304_1: RAD_R305.2 RAD_R307.2 | length 518.4
  Top Layer w6.69: RAD_R307.2@1286.61,821.65 1286.97,826.18 1289.37,856.3 1311.02,875.98 1311.02,895.67 1295.28,909.45 v6(1295.28,942.91)
  GND1 w6.69: v6(1295.28,942.91) v2(1393.7,944.88)
  GND2 w6.69: v2(1393.7,944.88) 1490.16,925.2 1588.58,830.71 1598.43,826.77 v9(1608.27,816.93)
  Bottom Layer w6.69: v9(1608.27,816.93) RAD_R305.2@1609.06,794.49
TI_NetR308_1: RAD_R310.2 RAD_R311.1 RAD_R313.2 | length 493.2
  Top Layer w7.09: v7(1139.76,876.97) 1148.62,885.83 1160.43,885.83 RAD_R311.1@1161.42,885.83
  SIG1 w7.09: v7(1125,1012.8) 1157.48,980.32 1201.77,980.32 1210.63,971.46 1210.63,947.83 v7(1139.76,876.97)
  Bottom Layer w7.09: v7(1125,1012.8) 1116.14,1003.94 RAD_R310.2@1102.36,1003.94 1101.38,1003.94 1101.87,1004.43 1104.33,1006.89 1104.33,1015.75 1110.24,1021.65 1110.24,1030.51 1125,1045.28 1125,1119.09 1122.05,1122.05 1122.05,1125 1083.66,1125 1080.71,1122.05 RAD_R313.2@1043.31,1122.05 ; RAD_R313.2@1043.31,1122.05 1042.32,1122.05 RAD_R313.2@1043.31,1122.05
TI_NetR380_2: RAD_U29.T13
TI_NetR381_2: RAD_U29.V12
TI_NetR386_2: RAD_R386.2 RAD_U29.D15 | length 1297.9
  Top Layer w6.69: v10(1675.69,1157.48) RAD_U29.D15@1676.41,1157.86
  GND1 w6.69: v2(1282.97,721.95) 1294.78,717.52 1370.08,721.95 1389.27,738.19 1504.43,732.28 1582.68,721.95 1774.61,724.9 1829.23,781 1827.76,803.15 1688.98,946.36 1683.07,1077.76 1660.93,1101.38 1659.45,1140.75 1662.4,1144.19 v10(1675.69,1157.48)
  GND2 w6.69: v11(1130.91,910.93) 1207.68,881.4 1228.35,845.96 1229.82,775.1 v2(1282.97,721.95)
  Bottom Layer w6.69: RAD_R386.2@1129.13,910.63 v11(1130.91,910.93)
TI_NetR392_2: RAD_U29.U16
TI_NetTP8_1: RAD_TP8.1 RAD_U8.22 | length 840.5
  Top Layer w6.69: v8(2004.92,699.8) 1999.02,699.8 RAD_TP8.1@1988.19,688.98 ; v8(2211.61,1254.92) 2267.72,1198.82 2267.72,1163.39 ; RAD_U8.22@2246.06,1122.05 2247.05,1122.05 RAD_U8.22@2252.95,1122.05 ; RAD_U8.22@2257.09,1122.24 2265.75,1126.97 2272.64,1133.86 2272.64,1158.46 2267.72,1163.39 ; 2270.67,1163.39 2267.72,1163.39 ; RAD_TP8.1@1988.19,688.98 1987.2,687.99 RAD_TP8.1@1988.19,688.98
  SIG2 w6.69: v8(2004.92,699.8) 2140.75,835.63 2140.75,1039.37 2211.61,1110.24 v8(2211.61,1254.92)
TI_NRSTOUT: RAD_R99.2 RAD_U8.6 | length 786.5
  Top Layer w6.69: RAD_U8.6@2097.64,1043.11 v12(2124.02,1016.73) ; v6(2335.43,872.44) 2385.83,872.44 2437.8,924.41 2437.01,952.76 2462.6,901.57 2469.49,897.64 2522.64,897.64 2529.53,901.57 2531.5,904.53 2531.5,952.76 RAD_R99.2@2500,984.25
  Top Layer w7.09: RAD_U8.6@2085.63,1043.31 2097.64,1043.31 RAD_U8.6@2097.64,1043.11
  GND1 w6.69: v12(2124.02,1016.73) 2127.56,886.61 2163.78,850.39 2313.39,850.39 v6(2335.43,872.44)
TI_OSC_CLK_OUT_ETHERNET: RAD_U29.B11
TI_OSC_CLKTOP: RAD_U29.A11
TI_PMIC_CLK: RAD_R75.1
TI_PMIC_CLK_OUT: RAD_R218.1 RAD_U29.T17 | length 420.5
  GND1 w6.69: v10(1371.48,1108.85) 1413.39,1063.98 1460.63,963.58 1461.61,955.71 1588.58,828.74 1594.49,827.76 1602.36,821.85 1605.32,815.94 v10(1614.17,778.74)
TI_PMIC_EN: RAD_R125.1 RAD_U8.15 | length 446
  Top Layer w6.69: 2225.13,962.11 v12(2243.11,980.32) 2243.11,954.72 2265.75,932.09 2265.75,903.54 2265.75,886.81 v12(2250,871.06) ; v6(2336.61,725.39) RAD_R125.1@2342.52,708.66
  GND1 w6.69: v12@2251.97,869.29 2314.96,900.79 2333.86,900.79 2352.76,881.89 2352.76,744.88 v6@2335.43,727.56
  other v6: 2225.58,983.08
TI_PMIC_NINT: RAD_R13.2 RAD_R17.2 RAD_R106.1 RAD_U8.7 | length 888.6
  Top Layer w6.69: v12(2053.15,1031.5) 2060.04,1018.7 RAD_U8.7@2083.17,1023.62
  Top Layer w7.09: RAD_R13.2@1771.65,984.25 1771.65,983.27 1786.42,968.5 1789.37,968.5 v6(1792.32,965.55) 1792.32,909.45 1768.7,885.83 1768.7,847.44 1807.09,809.06 1830.71,809.06 1866.14,773.62 1866.14,741.14 1869.09,738.19 1870.08,737.5 ; RAD_R106.1@1870.08,767.72 1870.08,737.5 ; RAD_R17.2@2047.24,688.98 2047.24,700 2023.32,723.92 1883.66,723.92 1870.08,737.5
  GND1 w6.69: v6(1792.32,965.55) 1798.43,959.06 1981.1,959.06 v12(2053.15,1031.5)
TI_PMIC_SPI_CLK: RAD_R63.2
TI_PMIC_SPI_CS0: RAD_R190.1
TI_PMIC_SPI_MISO: RAD_R193.2
TI_PMIC_SPI_MOSI: RAD_R186.2
TI_PMICOUT_1V0: RAD_C132.1 RAD_C134.1 RAD_L8.2 RAD_R71.2 RAD_R73.1 RAD_R111.1 | length 1452.9
  Top Layer w9.84: RAD_R111.1@1852.36,944.88 1851.38,944.88 1851.87,945.37 1866.14,959.65 1872.05,959.65 1875,962.6 1877.95,962.6 1880.91,965.55 1883.86,965.55 1886.81,968.5 1886.81,971.46 1889.76,974.41 1889.76,989.17 1910.43,1009.84 RAD_C134.1@1909.45,1008.86 ; v3(2161.42,897.64) 2164.37,900.59 2164.37,921.26 RAD_L8.2@2165.35,921.26
  Top Layer w15.75: v6(1903.54,1045.28) 1922.09,1017.22 RAD_C134.1@1935.24,997.34
  GND1 w15.75: v2(1826.77,1169.29) 1846.46,1149.61 1844.49,1096.46 1860.24,1084.65 v6(1903.54,1045.28)
  SIG1 w9.84: v2(2147.64,814.96) 2152.56,856.3 ; v3(2161.42,897.64) 2161.42,894.68 2152.56,885.83 2152.56,882.87 2149.61,879.92 2149.61,862.2 2152.56,859.25 2152.56,856.3 ; v7(2483.27,874.02) 2471.46,874.02 2465.55,868.11 2300.2,868.11 2288.39,856.3 2193.9,856.3 2185.04,847.44 2164.37,847.44 2161.42,850.39 2158.46,850.39 2152.56,856.3
  GND2 w15.75: v2(1826.77,1169.29) 1891.73,1125.98 v9(2082.68,935.04)
  Bottom Layer w9.84: RAD_R71.2@1952.36,733.86 2039.37,734.25 2120.08,814.96 v2(2147.64,814.96) ; RAD_R73.1@2458.66,846.46 2459.65,847.44 2477.36,865.16 2477.36,868.11 v7(2483.27,874.02)
  Bottom Layer w15.75: v9(2082.68,935.04) 2100.39,917.32 RAD_C132.1@2119.88,918.01
  Bottom Layer w21.65: RAD_C132.1@2145.67,906.5 v3(2161.42,897.64)
TI_PMICOUT_1V2: RAD_C129.1 RAD_C130.1 RAD_L2.2 RAD_R30.1 RAD_R32.1 RAD_R291.2 | length 2550.7
  Top Layer w9.84: RAD_R30.1@1043.31,891.73 1042.32,891.73 1042.32,865.16 v7(1060.04,847.44) ; v3(1833.66,897.64) 1845.47,909.45 1922.24,909.45 1928.15,903.54 1928.15,874.02 1954.72,847.44 RAD_C129.1@1953.74,846.46 ; v3(2320.87,1051.18) 2323.82,1048.23 2323.82,1027.56 RAD_L2.2@2322.83,1027.56
  SIG1 w9.84: v7(1060.04,847.44) 1068.9,838.58 1068.9,820.87 1071.85,817.91 1071.85,812.01 1172.24,711.61 1175.2,711.61 1231.3,655.51 1240.16,655.51 1251.97,643.7 1334.65,643.7 1340.55,637.8 1455.71,637.8 1467.52,625.98 1470.47,625.98 1473.43,623.03 1517.72,623.03 1523.62,617.13 1526.57,617.13 1529.53,614.17 1547.24,614.17 1550.2,617.13 1553.15,617.13 1559.06,623.03 1559.06,625.98 v7(1570.87,637.8) ; v3(1765.75,817.91) 1821.85,874.02 1821.85,885.83 v3(1833.66,897.64) ; v7(1999.02,1133.86) 2013.78,1133.86 2037.4,1157.48 2040.35,1157.48 2043.31,1160.43 2223.43,1160.43 2235.24,1172.24 2238.19,1172.24 2241.14,1175.2 2258.86,1175.2 2261.81,1172.24 2264.76,1172.24 2314.96,1122.05 2314.96,1057.09 v3(2320.87,1051.18)
  Bottom Layer w8.66: v3(1833.66,897.64) 1832.68,897.64 1840.55,905.51 1893.7,905.51 1895.67,907.48 1897.64,907.48 1899.61,909.45 1899.61,962.6 1905.51,968.5 1905.51,1011.81 1946.85,1053.15 1946.85,1055.12 RAD_C130.1@1948.82,1057.09
  Bottom Layer w9.84: RAD_R32.1@1515.75,708.66 RAD_R32.1@1514.76,708.66 ; v7(1570.87,637.8) 1573.82,634.84 1585.63,634.84 1597.44,623.03 1626.97,623.03 1629.92,625.98 1632.87,625.98 1635.83,628.94 1635.83,631.89 1638.78,634.84 1638.78,705.71 1635.83,708.66 1635.83,711.61 1632.87,711.61 1629.92,714.57 1591.54,714.57 1573.82,732.28 ; v3(1765.75,817.91) 1774.61,826.77 1774.61,829.72 RAD_R291.2@1786.42,841.54 ; RAD_C130.1@1948.82,1058.07 1948.82,1057.09 1949.31,1057.58 1999.02,1107.28 v7(1999.02,1133.86) ; RAD_R32.1@1514.76,708.66 1514.76,711.61 1529.53,726.38 ; RAD_R32.1@1514.76,708.66 1529.53,723.43 1529.53,726.38 ; 1529.53,726.38 1535.43,732.28 1573.82,732.28 ; 1573.82,732.28 1585.63,732.28 1594.49,723.43 1653.54,723.43 1671.26,705.71 1674.21,705.71 1677.17,702.76 1715.55,702.76 1733.27,685.04 1810.04,685.04 1815.94,690.94 1815.94,726.38 1810.04,732.28 1810.04,744.09 1786.42,767.72 RAD_R291.2@1786.42,841.54 ; RAD_R291.2@1786.42,841.54 RAD_R291.2@1791.34,846.46 ; RAD_R291.2@1791.34,846.46 1792.32,847.44 RAD_R291.2@1791.34,846.46
TI_PMICOUT_1V8: RAD_C60.1 RAD_C125.1 RAD_L9.2 RAD_R14.2 RAD_R104.1 | length 3793.3
  Top Layer w8.66: v8(1812.99,915.35) 1810.04,912.4 1810.04,891.73 1812.99,888.78 1812.99,882.87 1815.94,882.87 1815.94,879.92 1830.71,865.16 RAD_R14.2@1830.71,866.14 ; v8(1960.63,1021.65) 1960.63,1009.84 1963.58,1006.89
  Top Layer w9.84: RAD_C125.1@1948.82,1146.65 1948.82,1145.67 1948.82,1107.28 1951.77,1104.33 1951.77,1101.38 1954.72,1098.43 1954.72,1033.46 1963.58,1024.61 1963.58,1006.89 1981.3,989.17 1993.11,989.17 1999.02,983.27 2004.92,983.27 RAD_L9.2@2007.87,980.32
  Top Layer w15.75: v12(2559.06,926.18) RAD_R104.1@2570.87,926.18 v12(2578.74,926.18)
  PWR2 w15.75: v8(1960.63,1021.65) 1960.63,946.46 2045.67,861.42 2051.97,861.42 2121.26,792.13 2171.65,792.13 2212.6,751.18 2255.91,726.38 2271.65,726.38 2557.48,751.18 2620.47,814.17 2620.47,844.09 v14(2677.17,901.57)
  GND1 w15.75: v12(2559.06,926.18) v12(2578.74,926.18) v14(2677.17,901.57)
  SIG2 w8.66: v2(773.62,2176.18) 1092.52,2176.18 1210.63,2294.29 1231.3,2294.29 1340.55,2185.04 1340.55,1886.81 1706.69,1520.67 1706.69,1189.96 1683.07,1166.34 1658.46,1142.72 1658.46,1069.88 1683.07,1045.28 v8(1812.99,915.35) 1860.24,962.6 1901.57,962.6 v8(1960.63,1021.65)
  Bottom Layer w8.66: RAD_C60.1@728.35,2196.85 729.33,2196.85 741.14,2185.04 764.76,2185.04 v2(773.62,2176.18)
TI_PVIN3V3: RAD_C3.2 RAD_C6.2 RAD_C8.2 RAD_C9.1 RAD_C9.3 RAD_C15.1 RAD_C31.1 RAD_C58.1 RAD_C58.3 RAD_C143.1 RAD_C144.2 RAD_C153.2 RAD_C199.1 RAD_C200.1 RAD_C201.1 RAD_C202.1 RAD_L1.2 RAD_R125.2 RAD_R200.2 RAD_U8.13 RAD_U8.20 RAD_U8.25 RAD_U8.27 | length 3981.7
  Top Layer w7.48: RAD_U8.27@2145.67,1138.78 2145.67,1164.37 v24(2161.42,1190.75) 2185.04,1167.13 RAD_U8.25@2185.04,1138.78 ; RAD_U8.20@2245.08,1082.68 v24(2277.36,1082.68)
  Top Layer w9.84: RAD_C9.1@1830.71,1031.5 1830.71,1030.51 1830.22,1031 1818.9,1042.32 1798.23,1042.32 1795.28,1045.28 1795.28,1048.23 1792.32,1051.18 1792.32,1074.8 1795.28,1077.76 1795.28,1080.71 1798.23,1083.66 RAD_C9.3@1818.9,1083.66 ; RAD_C9.3@1830.71,1094.49 RAD_C9.3@1830.71,1095.47 ; v3(1869.09,1110.24) 1842.52,1083.66 RAD_C9.3@1818.9,1083.66 ; RAD_C15.1@1870.08,1151.57 1869.09,1151.57 1866.14,1148.62 1866.14,1130.91 RAD_C9.3@1830.71,1095.47 ; v3(2046.26,1065.94) RAD_L1.2@2007.87,1027.56 2028.54,1006.89 2043.31,1006.89 2046.26,1003.94 2049.21,1003.94 2052.17,1000.98 2052.17,918.31 2054.92,915.55 2055.12,915.35 v3(2055.91,916.54) ; RAD_C202.1@2111.22,787.4 2111.22,788.39 2173.23,726.38 2173.23,720.47 RAD_C200.1@2185.04,708.66 2220.47,708.66 2226.38,714.57 2261.81,714.57 RAD_C153.2@2294.29,747.05 ; RAD_C201.1@2249.02,826.77 RAD_C201.1@2250,826.77 ; RAD_C143.1@2362.2,979.33 2362.2,980.32 2294.29,912.4 RAD_C6.2@2294.29,906.5 ; RAD_R125.2@2381.89,708.66 2382.87,708.66 RAD_C31.1@2382.87,776.57 ; RAD_C31.1@2381.89,777.56 RAD_C31.1@2382.87,776.57 ; v3(2433.07,782.48) 2427.17,776.57 RAD_C31.1@2382.87,776.57 ; RAD_C9.3@1818.9,1083.66 1830.22,1094.98 RAD_C9.3@1830.71,1095.47 ; RAD_C201.1@2250,826.77 2294.29,782.48 RAD_C153.2@2294.29,748.03 ; RAD_C201.1@2250,826.77 2294.29,871.06 RAD_C6.2@2294.29,905.51 ; RAD_C153.2@2294.29,747.05 2353.35,747.05 RAD_C31.1@2382.87,776.57 ; RAD_C153.2@2294.29,747.05 RAD_C153.2@2294.29,748.03 ; RAD_C153.2@2294.29,747.05 RAD_C153.2@2294.29,748.03 ; RAD_C6.2@2294.29,905.51 RAD_C6.2@2294.29,906.5 ; RAD_C6.2@2294.29,905.51 RAD_C6.2@2294.29,906.5
  Top Layer w17.72: v3(2055.91,916.54) RAD_C8.2@2086.61,916.34 ; RAD_C6.2@2294.29,912.4 v3(2294.29,937.8) ; v3(2428.35,1271.65) 2446.06,1289.37 RAD_C3.2@2472.44,1289.37
  PWR1 w21.65: v3(2055.91,916.54) 2086.61,1009.84 2354.33,1161.42 v3(2428.35,1271.65)
  PWR1 w29.53: v24(2161.42,1190.75) 2119.09,1148.62 2091.54,1087.6 2086.61,1009.84 ; v24(2277.36,1082.68) 2086.61,1009.84 ; v3(2294.29,937.8) 2086.61,1009.84
  PWR1 w33.46: v3(1846.46,830.71) v3(1870.08,818.9) v3(1897.64,818.9)
  PWR1 w88.58: v3(1870.08,818.9) 1885.58,832.57 2023.05,953.79 2086.61,1009.84
  GND1 w11.81: v12(2185.04,998.03) 2186.13,970.52 2186.52,960.63 2188.98,954.23 2200.3,942.42 2289.86,942.42 v3(2294.29,937.8)
  SIG1 w9.84: v3(1869.09,1110.24) 2001.97,1110.24 2016.73,1095.47 2019.68,1095.47 2043.31,1071.85 2043.31,1068.9 v3(2046.26,1065.94) ; v3(2430.12,806.1) 2433.07,803.15 v3(2433.07,782.48)
  SIG2 w8.66: v8(2047.24,1248.03) 2104.33,1248.03 2161.42,1190.94 v24(2161.42,1190.75)
  Bottom Layer w8.66: v8(2047.24,1248.03) 2055.12,1240.16 RAD_C144.2@2077.76,1240.16 ; RAD_C144.2@2077.76,1240.16 2078.74,1240.16 RAD_C144.2@2077.76,1240.16
  Bottom Layer w9.84: RAD_C58.3@1897.64,787.4 1898.62,788.39 v3@1898.62,817.91 ; v3(1897.64,818.9) v3@1898.62,817.91 ; RAD_C58.1@1960.63,787.4 1960.63,788.39 1963.58,791.34 1963.58,797.24 1993.11,826.77 1993.11,874.02 1987.2,879.92 1910.43,879.92 1898.62,868.11 v3@1898.62,817.91 ; v3(2430.12,806.1) 2441.93,806.1 2459.65,788.39 RAD_C199.1@2460.63,787.4
  Bottom Layer w21.65: v3(1846.46,830.71) RAD_R200.2@1870.08,854.33 ; RAD_R200.2@1870.08,846.46 v3(1897.64,818.9)
  Bottom Layer w29.53: v3(1870.08,818.9) 1870.08,846.46 1870.08,854.33 RAD_R200.2@1870.08,868.11
  other v12: 2185.04,970.47
TI_QSPI_CS: RAD_R38.1 RAD_U1.1 RAD_U29.U12 | length 701.2
  Top Layer w6.69: RAD_R38.1@1122.05,1594.49 v6(1142.72,1589.57) ; v6(1142.72,1537.4) RAD_U1.1@1157.48,1525.59
  Top Layer w7.09: RAD_U1.1@1157.68,1524.67 1157.48,1525.59 1175.2,1507.87 1175.2,1480.32 v2(1222.44,1433.07)
  GND1 w6.69: v6(1142.72,1537.4) v6(1142.72,1589.57)
  GND1 w7.09: v2(1296.26,1114.17) 1345.47,1181.1 v10(1345.89,1236.8)
  SIG2 w7.09: v2(1222.44,1433.07) 1222.44,1187.01 v2(1296.26,1114.17)
TI_QSPI_D0: RAD_R45.2 RAD_U29.U11
  other v14: 1345.89,1262.39
TI_QSPI_D0_FLASH: RAD_R45.1 RAD_U1.5 | length 1317.4
  Top Layer w6.69: v6(992.13,1306.1) RAD_U1.5@1007.03,1309.82 ; v6(1001.97,1331.69) RAD_U1.5@1007.03,1309.83 ; RAD_U1.5@1007.68,1309.98 RAD_U1.5@1007.03,1309.82 ; RAD_U1.5@1010.54,1294.69 RAD_U1.5@1007.03,1309.82
  PWR1 w6.69: v2(884.84,1343.5) 858.27,1368.11 858.27,1423.23 1082.68,1647.64 1082.68,1775.59 v2(1087.6,1779.53)
  GND1 w6.69: v2(884.84,1309.06) 897.64,1301.18 984.25,1301.18 v6@988.52,1305.45 ; v2(884.84,1343.5) 912.4,1342.52 968.5,1304.13 981.3,1304.13 v6@988.52,1305.45 ; v6(992.13,1306.1) v6@988.52,1305.45 ; v6(1001.97,1331.69) 1000,1329.72 1000,1316.93 v6@988.52,1305.45 ; v2@1083.66,1775.59 v2(1087.6,1779.53)
  GND2 w6.69: v2(884.84,1309.06) 903.54,1290.35 v9(973.43,1290.35)
  Bottom Layer w6.69: v9(973.43,1290.35) 1092.52,1290.35 1119.09,1263.78 RAD_R45.1@1322.08,1263.57
TI_QSPI_D1: RAD_R39.1 RAD_R49.1 RAD_U29.V11 | length 942.2
  Top Layer w6.69: RAD_R39.1@1072.83,1228.35 v6(1084.65,1234.25) ; v6(1233.27,1584.65) RAD_R49.1@1250,1584.65 v6(1266.73,1572.83) ; v6(1309.06,1254.92) RAD_U29.V11@1320.3,1262.39
  GND1 w6.69: v6(1084.65,1234.25) 1108.27,1203.74 1115.16,1199.8 1128.94,1199.8 1200.79,1229.33 1208.66,1239.17 1203.74,1429.13 1203.74,1555.12 v6(1233.27,1584.65) ; v6(1266.73,1572.83) 1250.98,1352.36 1233.27,1308.07 1233.27,1293.31 1237.2,1286.42 v6(1309.06,1254.92)
TI_QSPI_D1_FLASH: RAD_R39.2 RAD_U1.2 | length 747.9
  GND1 w6.69: v2(926.67,1599.9) 926.67,1586.12 1006.89,1503.94 v10(1074.02,1252.17) ; v2(1043.31,1658.46) v10(1103.82,1524.67)
  GND2 w6.69: v2(926.67,1599.9) 931.59,1580.71 962.11,1553.15 985.73,1553.15 1043.31,1617.62 v2(1043.31,1658.46)
TI_QSPI_D2: RAD_R42.1 RAD_R43.1 RAD_U29.T11 | length 765.2
  Top Layer w7.09: v2(887.99,1366.54) 870.08,1370.37 859.84,1380.61 859.84,1448.43 RAD_R42.1@915.35,1503.94 ; v2(1177.17,1284.65) v10(1250,1299.21) ; v6(1253.94,1312.99) 1254.7,1299.48 RAD_R43.1@1255.12,1292.13
  GND1 w7.09: v6(1253.94,1312.99) 1272.64,1331.69 1324.8,1331.69 1328.74,1330.22 1335.63,1324.31 1338.58,1317.42 1338.58,1296.26 v10(1371.48,1262.39)
  SIG1 w7.09: v2(887.99,1366.54) 969.88,1284.65 v2(1177.17,1284.65)
TI_QSPI_D2_FLASH: RAD_R42.2 RAD_U1.3 | length 208.5
  Top Layer w7.09: RAD_R42.2@915.35,1527.56 v2(977.56,1571.26) ; RAD_U1.3@1057.68,1524.67 v2(1058.17,1576.38)
  SIG2 w7.09: v2(977.56,1571.26) v2(1058.17,1576.38)
TI_QSPI_D3: RAD_R40.2 RAD_R41.1 RAD_U29.R12 | length 837.6
  Top Layer w6.69: v6(1010.83,1606.3) RAD_R40.2@1023.62,1606.3 ; RAD_R41.1@1171.26,1240.16 1178,1241.76 v6(1191.93,1245.08) ; v10(1178.15,1241.14) 1192.07,1241.72 v6(1225.39,1243.11)
  GND1 w6.69: v6(1010.83,1606.3) 1141.73,1320.87 1161.42,1273.62 v6(1191.93,1245.08) v10(1178.15,1241.14) ; v2(1186.02,1145.67) v6(1225.39,1243.11)
  GND2 w6.69: v2(1186.02,1145.67) v14(1397.08,1236.8)
TI_QSPI_D3_FLASH: RAD_R40.1 RAD_U1.7 | length 444.2
  Top Layer w7.09: v2(995.47,1628.84) 1033.86,1622.44 1040.26,1616.04 1040.26,1596.85 RAD_R40.1@1023.62,1582.68 ; RAD_U1.7@1107.68,1309.98 v2(1123.43,1315.35)
  SIG1 w7.09: v2(995.47,1628.84) v2(1123.43,1315.35)
TI_QSPI_SCLK: RAD_R44.2 RAD_U29.R10 | length 623.1
  Top Layer w6.69: v6(1389.76,1299.21) RAD_U29.R10@1397.08,1287.98
  GND1 w6.69: v10(1003.94,1251.97) 1013.78,1317.91 1015.75,1321.85 v2(1033.46,1333.66) ; v6(1389.76,1299.21) 1415.35,1361.22 1415.35,1373.03 v2(1393.7,1412.4)
  Bottom Layer w6.69: v2(1033.46,1333.66) 1112.2,1413.39 v2(1393.7,1412.4)
TI_QSPI_SCLK_FLASH: RAD_R44.1 RAD_U1.6 | length 147.1
  Top Layer w7.09: v2(976.28,1265.45) 976.28,1253.94 1001.87,1228.35 RAD_R44.1@1003.94,1228.35 ; v2(1031.3,1310.24) RAD_U1.6@1057.68,1309.98
  SIG2 w7.09: v2(976.28,1265.45) v2(1031.3,1310.24)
